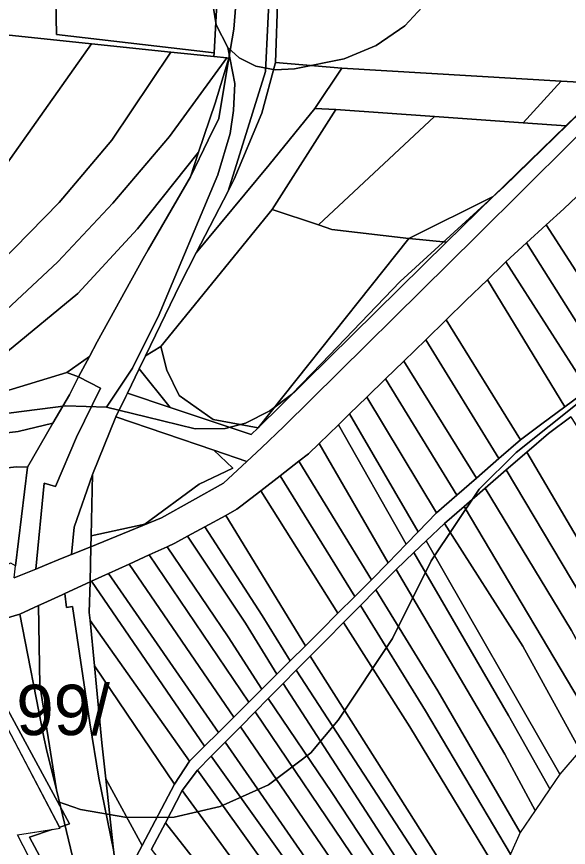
# Model space of a CAD drawing. Extents: x -535894 to -532827, y -1165802 to -1163635.
# Drawn here: x -534273.9 to -534109.5, y -1165431.5 to -1165184 of the extents above; entities that cross this region are included whole.
import ezdxf

# ---------------------------------------------------------------- set-up
doc = ezdxf.new("R2010")
doc.units = 0
for name, color, linetype in [('BPEJ_s', 7, 'Continuous'), ('orna_s', 7, 'Continuous'), ('ostatni_s', 7, 'Continuous'), ('trav_porost_s', 7, 'Continuous'), ('voda_s', 7, 'Continuous')]:
    doc.layers.add(name, color=color, linetype=linetype)

msp = doc.modelspace()

# ---------------------------------------------------------------- linework, layer by layer
at = {"layer": 'BPEJ_s'}
for points in [[(-534128.66, -1165234.701), (-534052.52, -1165160.48), (-533990.56, -1165093.1), (-533942.78, -1165048.02), (-533910.29, -1165011.39), (-533882.731, -1164977.94), (-533858.68, -1164945.769), (-533840.52, -1164915.19)], [(-534304.992, -1164938.782), (-534306.367, -1164946.177), (-534306.73, -1164953.69), (-534305.985, -1164961.176), (-534303.23, -1164969.461), (-534299.169, -1164977.19), (-534280.436, -1165000.199), (-534268.11, -1165013.02), (-534257.59, -1165027.36), (-534248.679, -1165043.835), (-534244.462, -1165051.631), (-534227.57, -1165100.31), (-534222.071, -1165116.16), (-534218.09, -1165134.31), (-534216.18, -1165149.679), (-534216.18, -1165167.13), (-534215.59, -1165178.943), (-534214.43, -1165186.48), (-534210.92, -1165193.25), (-534208.85, -1165204), (-534209.25, -1165212.04), (-534210.291, -1165218.89)], [(-534052.52, -1165160.48), (-534128.66, -1165234.701), (-534159.56, -1165262.93), (-534183.05, -1165287.34), (-534191.96, -1165296.599), (-534198.42, -1165301.519), (-534205.67, -1165305.18), (-534211.72, -1165306.77), (-534220.661, -1165306.853), (-534235.298, -1165303.278), (-534247.08, -1165300.4), (-534239.36, -1165288.81), (-534232.654, -1165275.407), (-534231.71, -1165273.52), (-534213.95, -1165231.16), (-534210.291, -1165218.89), (-534209.25, -1165212.04), (-534208.85, -1165204), (-534210.92, -1165193.25), (-534207.58, -1165196.35), (-534202.56, -1165198.82), (-534196.866, -1165199.921), (-534191.077, -1165199.577), (-534176.28, -1165196.59), (-534166.72, -1165192.69), (-534158.213, -1165186.838), (-534153.03, -1165181.22)], [(-533970.41, -1165171.07), (-533985.872, -1165188.218), (-533999.16, -1165206.031), (-534009.91, -1165220.44), (-534020.91, -1165231.99), (-534035.084, -1165244.865), (-534056.9, -1165261.54), (-534075.955, -1165274.993), (-534079.332, -1165277.377), (-534105.4, -1165298.17), (-534125.07, -1165313.86), (-534136.06, -1165324.773), (-534150.4, -1165346.2), (-534161.87, -1165369.29), (-534178.11, -1165393.66), (-534186.226, -1165403.375), (-534198.82, -1165412.93), (-534213.249, -1165419.389), (-534226.966, -1165422.497), (-534241.03, -1165422.65), (-534254.891, -1165420.26), (-534261.74, -1165417.867), (-534281.75, -1165380.99)], [(-534136.06, -1165324.773), (-534125.07, -1165313.86), (-534105.4, -1165298.17), (-534079.332, -1165277.377), (-534075.955, -1165274.993), (-534056.9, -1165261.54), (-534035.084, -1165244.865), (-534020.91, -1165231.99), (-534009.91, -1165220.44), (-533999.16, -1165206.031), (-533985.872, -1165188.218), (-533970.41, -1165171.07)], [(-534153.03, -1165181.22), (-534158.213, -1165186.838), (-534166.72, -1165192.69), (-534176.28, -1165196.59), (-534191.077, -1165199.577), (-534196.866, -1165199.921), (-534202.56, -1165198.82), (-534207.58, -1165196.35), (-534210.92, -1165193.25), (-534214.43, -1165186.48), (-534215.59, -1165178.943)], [(-534210.291, -1165218.89), (-534213.95, -1165231.16), (-534231.71, -1165273.52), (-534232.654, -1165275.407), (-534239.36, -1165288.81), (-534247.08, -1165300.4), (-534259.201, -1165299.977), (-534288.01, -1165303.627)], [(-534504, -1165364.91), (-534479.15, -1165348.82), (-534459.071, -1165335.819), (-534440.92, -1165327.96), (-534400.789, -1165317.92), (-534366.86, -1165313.619), (-534340.91, -1165310.331), (-534288.01, -1165303.627), (-534259.201, -1165299.977), (-534247.08, -1165300.4), (-534235.298, -1165303.278), (-534220.661, -1165306.853), (-534211.72, -1165306.77), (-534205.67, -1165305.18), (-534198.42, -1165301.519), (-534191.96, -1165296.599), (-534183.05, -1165287.34), (-534159.56, -1165262.93), (-534128.66, -1165234.701)], [(-534254.02, -1165458.36), (-534270, -1165428.46), (-534263.286, -1165426.218), (-534260.88, -1165425.85), (-534261.074, -1165425.479), (-534260.433, -1165425.265), (-534258.14, -1165424.5), (-534261.74, -1165417.867), (-534254.891, -1165420.26), (-534241.03, -1165422.65), (-534226.966, -1165422.497), (-534213.249, -1165419.389), (-534198.82, -1165412.93), (-534186.226, -1165403.375), (-534178.11, -1165393.66), (-534161.87, -1165369.29), (-534150.4, -1165346.2), (-534136.06, -1165324.773)], [(-534013.02, -1165333.89), (-534079.092, -1165382.22), (-534081.89, -1165384.25), (-534087.82, -1165388.56), (-534094.23, -1165393.22), (-534100.32, -1165397.66), (-534105.93, -1165402.64), (-534112, -1165409.73), (-534115, -1165414.12), (-534119.41, -1165420.59), (-534123.86, -1165427.13), (-534126.75, -1165433.55)]]:
    msp.add_lwpolyline(points, dxfattribs=at)
for points in [[(-534260.433, -1165425.265), (-534261.074, -1165425.479), (-534278.69, -1165391.9), (-534289.827, -1165368.435), (-534289.197, -1165368.215), (-534287.26, -1165367.54), (-534281.75, -1165380.99), (-534261.74, -1165417.867), (-534258.14, -1165424.5)], [(-534221.041, -1165492.816), (-534221.281, -1165493.132), (-534234.3, -1165490.14), (-534242.12, -1165462.96), (-534244.14, -1165462.64), (-534249.66, -1165461.74), (-534253.34, -1165461.15), (-534256.73, -1165460.61), (-534273.58, -1165427.79), (-534263.286, -1165426.218), (-534270, -1165428.46), (-534254.02, -1165458.36), (-534247.37, -1165459.96), (-534241.8, -1165460.84), (-534239.62, -1165461.22), (-534239.05, -1165464.37), (-534233.37, -1165489.25), (-534231.05, -1165489.74), (-534220.2, -1165491.71)]]:
    msp.add_lwpolyline(points, close=True, dxfattribs=at)
at = {"layer": 'orna_s'}
for points in [[(-534196.09, -1165177.34), (-534144.9, -1165178.54), (-534107.5, -1165181.08), (-534103.37, -1165181.48), (-534078.8, -1165183.83), (-534077.66, -1165183.91), (-534078.91, -1165185.19), (-534097.29, -1165204.09), (-534111.65, -1165203.25), (-534176.94, -1165199.42), (-534196.74, -1165197.75)], [(-534196.74, -1165197.75), (-534176.94, -1165199.42), (-534185.07, -1165211.45), (-534198.6, -1165228.24), (-534220.39, -1165254.46), (-534210.89, -1165236.07), (-534209.06, -1165232.51), (-534200.78, -1165212.83)], [(-534176.94, -1165199.42), (-534111.65, -1165203.25), (-534122.97, -1165215.71), (-534149.39, -1165213.83), (-534178.75, -1165211.76), (-534185.07, -1165211.45)], [(-534111.65, -1165203.25), (-534097.29, -1165204.09), (-534110.19, -1165216.6), (-534122.97, -1165215.71)], [(-534178.75, -1165211.76), (-534149.39, -1165213.83), (-534183.96, -1165246.08), (-534197.75, -1165241.47)], [(-534149.39, -1165213.83), (-534122.97, -1165215.71), (-534110.19, -1165216.6), (-534131.84, -1165237.61), (-534157.06, -1165250.17), (-534179.96, -1165247.42), (-534183.96, -1165246.08)], [(-534105.03, -1165235.88), (-534078.3, -1165276.29), (-534085.13, -1165281.37), (-534090.65, -1165285.49), (-534116.12, -1165246.09), (-534110.88, -1165241.27)], [(-534197.75, -1165241.47), (-534183.96, -1165246.08), (-534179.96, -1165247.42), (-534157.06, -1165250.17), (-534201.96, -1165306.58), (-534215.31, -1165304.06), (-534225.42, -1165296.87), (-534229.16, -1165289.39), (-534230.92, -1165282.33)], [(-534116.12, -1165246.09), (-534090.65, -1165285.49), (-534097.28, -1165290.43), (-534121.92, -1165251.44)], [(-534121.92, -1165251.44), (-534097.28, -1165290.43), (-534103.68, -1165295.19), (-534128.1, -1165257.13)], [(-534128.1, -1165257.13), (-534103.68, -1165295.19), (-534110.5, -1165300.26), (-534133.62, -1165262.47), (-534128.78, -1165257.75)], [(-534140, -1165268.66), (-534133.62, -1165262.47), (-534110.5, -1165300.26), (-534117.37, -1165305.37), (-534123.72, -1165310.1), (-534145.91, -1165274.41)], [(-534151.99, -1165280.33), (-534145.91, -1165274.41), (-534123.72, -1165310.1), (-534130.19, -1165315.73)], [(-534158.49, -1165286.65), (-534151.99, -1165280.33), (-534130.19, -1165315.73), (-534136.84, -1165321.5)], [(-534163.98, -1165291.99), (-534158.49, -1165286.65), (-534136.84, -1165321.5), (-534142.7, -1165326.58)], [(-534169.57, -1165297.42), (-534163.98, -1165291.99), (-534142.7, -1165326.58), (-534148.81, -1165331.89)], [(-534174.7, -1165302.41), (-534169.57, -1165297.42), (-534148.81, -1165331.89), (-534154.19, -1165337.49)], [(-534178, -1165305.62), (-534174.7, -1165302.41), (-534154.19, -1165337.49), (-534157.81, -1165341.24)], [(-534183.78, -1165311.24), (-534178, -1165305.62), (-534157.81, -1165341.24), (-534163.15, -1165346.78)], [(-534186.9, -1165314.27), (-534183.78, -1165311.24), (-534163.15, -1165346.78), (-534168.1, -1165351.81), (-534189.75, -1165316.48)], [(-534195.4, -1165320.86), (-534189.75, -1165316.48), (-534168.1, -1165351.81), (-534173.09, -1165356.78)], [(-534201.15, -1165325.32), (-534195.4, -1165320.86), (-534173.09, -1165356.78), (-534178.13, -1165361.8)], [(-534207.06, -1165329.91), (-534201.15, -1165325.32), (-534178.13, -1165361.8), (-534183.26, -1165366.91), (-534187.85, -1165371.47), (-534211.58, -1165332.65), (-534208.23, -1165330.82)], [(-534217.81, -1165336.04), (-534211.58, -1165332.65), (-534187.85, -1165371.47), (-534192.38, -1165376), (-534200.7, -1165362.44)], [(-534223, -1165338.87), (-534217.81, -1165336.04), (-534200.7, -1165362.44), (-534192.38, -1165376), (-534196.33, -1165379.94), (-534205.7, -1165364.73)], [(-534226.73, -1165340.9), (-534223, -1165338.87), (-534205.7, -1165364.73), (-534196.33, -1165379.94), (-534200.8, -1165384.39), (-534210.88, -1165368.77), (-534229.05, -1165341.96)], [(-534234.4, -1165344.4), (-534229.05, -1165341.96), (-534210.88, -1165368.77), (-534200.8, -1165384.39), (-534204.72, -1165388.29)], [(-534240.38, -1165347.14), (-534234.4, -1165344.4), (-534204.72, -1165388.29), (-534209.19, -1165392.73)], [(-534246.5, -1165349.94), (-534240.38, -1165347.14), (-534209.19, -1165392.73), (-534213.76, -1165397.27)]]:
    msp.add_lwpolyline(points, close=True, dxfattribs=at)
at = {"layer": 'ostatni_s'}
for points in [[(-534197.6, -1165157.43), (-534199.71, -1165200.4), (-534210.89, -1165236.07), (-534220.39, -1165254.46), (-534225.18, -1165263.79), (-534235.49, -1165285.14), (-534237.36, -1165289.01), (-534240.88, -1165296.25), (-534241.33, -1165297.17), (-534244.31, -1165303.28), (-534251.27, -1165320.44), (-534256.77, -1165336.1), (-534257.49, -1165344.29), (-534260.27, -1165345.42), (-534265.54, -1165347.57), (-534268.13, -1165348.62), (-534265.69, -1165323.08), (-534262.28, -1165324.03), (-534256.03, -1165309.32), (-534248.87, -1165294.69), (-534255.45, -1165291.38), (-534252.19, -1165285.28), (-534249.84, -1165280.89), (-534236.16, -1165256.09), (-534234.65, -1165253.49), (-534222.12, -1165231.81), (-534216.81, -1165220.86), (-534213.66, -1165214.35), (-534210.61, -1165196.44), (-534209.14, -1165187.8), (-534208.19, -1165175.29)], [(-534066.72, -1165179.82), (-534136.8, -1165249.37), (-534194.29, -1165306.12), (-534200.89, -1165312.54), (-534205.31, -1165316.61), (-534215.14, -1165313.24), (-534244.31, -1165303.28), (-534241.33, -1165297.17), (-534240.88, -1165296.25), (-534228.15, -1165300.5), (-534203.98, -1165308.56), (-534201.96, -1165306.58), (-534145.83, -1165251.25), (-534131.84, -1165237.61), (-534110.19, -1165216.6), (-534097.29, -1165204.09), (-534078.91, -1165185.19), (-534077.66, -1165183.91)], [(-534306.94, -1165304.65), (-534258.88, -1165290.11), (-534255.45, -1165291.38), (-534258.18, -1165296.74), (-534263.07, -1165305.2), (-534273.43, -1165307.68), (-534336.76, -1165315.12)], [(-534243.4, -1165444.03), (-534236.52, -1165431.02), (-534226.8, -1165412.68), (-534222.38, -1165405.86), (-534217.91, -1165401.41), (-534213.76, -1165397.27), (-534209.19, -1165392.73), (-534204.72, -1165388.29), (-534200.8, -1165384.39), (-534196.33, -1165379.94), (-534192.38, -1165376), (-534187.85, -1165371.47), (-534183.26, -1165366.91), (-534178.13, -1165361.8), (-534173.09, -1165356.78), (-534168.1, -1165351.81), (-534163.15, -1165346.78), (-534157.81, -1165341.24), (-534154.19, -1165337.49), (-534148.81, -1165331.89), (-534142.7, -1165326.58), (-534136.84, -1165321.5), (-534130.19, -1165315.73), (-534123.72, -1165310.1), (-534117.37, -1165305.37), (-534110.5, -1165300.26), (-534103.68, -1165295.19)], [(-534108.76, -1165303.24), (-534115.44, -1165308.22), (-534121.89, -1165313.8), (-534128.01, -1165319.11), (-534134.26, -1165324.52), (-534140.55, -1165329.98), (-534146.4, -1165335.06), (-534151.85, -1165340.25), (-534155.49, -1165343.73), (-534160.76, -1165348.75), (-534166.84, -1165354.83), (-534171.44, -1165359.48), (-534176.44, -1165364.53), (-534181.53, -1165369.66), (-534186.43, -1165374.61), (-534190.57, -1165378.79), (-534194.5, -1165382.75), (-534198.92, -1165387.21), (-534202.8, -1165391.13), (-534207.22, -1165395.6), (-534211.75, -1165400.17), (-534215.9, -1165404.37), (-534220.02, -1165408.52), (-534224.52, -1165414.59), (-534229.56, -1165424.19), (-534233.69, -1165432.05)], [(-534551.38, -1165379.05), (-534422.4, -1165326.53), (-534364.57, -1165315.97), (-534336.76, -1165315.12), (-534273.43, -1165307.68), (-534263.07, -1165305.2), (-534270.61, -1165318.24), (-534273.89, -1165318.16), (-534312.18, -1165322.29), (-534336.67, -1165324.94), (-534360.45, -1165326.25), (-534364.65, -1165326.48), (-534419.17, -1165333.25), (-534502.24, -1165366.65)]]:
    msp.add_lwpolyline(points, dxfattribs=at)
for points in [[(-534213.26, -1165156.72), (-534209.51, -1165156.58), (-534208.19, -1165175.29), (-534209.14, -1165187.8), (-534210.61, -1165196.44), (-534211.25, -1165196.37), (-534215.09, -1165195.97), (-534215.04, -1165194.82), (-534213.98, -1165174.68)], [(-534196.09, -1165177.34), (-534196.74, -1165197.75), (-534200.78, -1165212.83), (-534209.06, -1165232.51), (-534210.89, -1165236.07), (-534199.71, -1165200.4), (-534197.6, -1165157.43)], [(-534214.76, -1165209.81), (-534210.61, -1165196.44), (-534213.66, -1165214.35), (-534216.81, -1165220.86), (-534222.12, -1165231.81), (-534219.65, -1165224.42)], [(-534185.07, -1165211.45), (-534178.75, -1165211.76), (-534197.75, -1165241.47), (-534230.92, -1165282.33), (-534235.49, -1165285.14), (-534225.18, -1165263.79), (-534220.39, -1165254.46), (-534198.6, -1165228.24)], [(-534235.49, -1165285.14), (-534230.92, -1165282.33), (-534229.16, -1165289.39), (-534225.42, -1165296.87), (-534215.31, -1165304.06), (-534201.96, -1165306.58), (-534203.98, -1165308.56), (-534228.15, -1165300.5), (-534237.36, -1165289.01)], [(-534240.88, -1165296.25), (-534237.36, -1165289.01), (-534228.15, -1165300.5)], [(-534248.87, -1165294.69), (-534256.03, -1165309.32), (-534262.28, -1165324.03), (-534265.69, -1165323.08), (-534268.13, -1165348.62), (-534274.64, -1165351.27), (-534274.2, -1165347.69), (-534270.61, -1165318.24), (-534263.07, -1165305.2), (-534258.18, -1165296.74), (-534255.45, -1165291.38)], [(-534215.14, -1165313.24), (-534209.48, -1165318.59), (-534219.52, -1165323.38), (-534235.68, -1165335.21), (-534251.69, -1165338.72), (-534251.27, -1165320.44), (-534244.31, -1165303.28)], [(-534205.31, -1165316.61), (-534212.27, -1165323.02), (-534230.69, -1165333.38), (-534251.77, -1165341.96), (-534251.69, -1165338.72), (-534235.68, -1165335.21), (-534219.52, -1165323.38), (-534209.48, -1165318.59), (-534215.14, -1165313.24)], [(-534273.89, -1165318.16), (-534270.61, -1165318.24), (-534274.2, -1165347.69), (-534275.59, -1165346.89), (-534279.12, -1165348.18), (-534284.53, -1165354.73), (-534300.23, -1165360.21), (-534301.65, -1165360.47), (-534307.88, -1165340.19), (-534312.18, -1165322.29)], [(-534256.77, -1165336.1), (-534251.27, -1165320.44), (-534251.69, -1165338.72), (-534251.77, -1165341.96), (-534257.49, -1165344.29)], [(-534259.48, -1165355.88), (-534252.01, -1165352.47), (-534252.23, -1165361.54), (-534251.99, -1165363.99), (-534250.69, -1165377.47), (-534248.48, -1165400.41), (-534247.31, -1165411.07), (-534244.98, -1165432.27), (-534249.38, -1165410.91), (-534252.04, -1165394.43), (-534257.28, -1165359.81), (-534259.04, -1165360.05)], [(-534260.34, -1165356.27), (-534259.48, -1165355.88), (-534259.04, -1165360.05), (-534257.28, -1165359.81), (-534252.04, -1165394.43), (-534249.38, -1165410.91), (-534244.98, -1165432.27), (-534243.4, -1165444.03), (-534242.7, -1165449.22), (-534241.22, -1165460.36), (-534234.3, -1165490.14), (-534242.12, -1165462.96), (-534244.14, -1165462.64), (-534249.66, -1165461.74), (-534253.34, -1165461.15), (-534257.19, -1165434.29), (-534262.04, -1165414.36), (-534266.94, -1165383.2), (-534267.32, -1165359.47), (-534265.74, -1165358.75), (-534264.71, -1165358.28)], [(-534272.9, -1165362.02), (-534267.32, -1165359.47), (-534266.94, -1165383.2), (-534262.04, -1165414.36), (-534264.94, -1165402.42), (-534265.72, -1165399.2)], [(-534272.9, -1165362.02), (-534265.72, -1165399.2), (-534264.94, -1165402.42), (-534262.04, -1165414.36), (-534257.19, -1165434.29), (-534253.34, -1165461.15), (-534256.73, -1165460.61), (-534273.58, -1165427.79), (-534260.88, -1165425.85), (-534278.69, -1165391.9), (-534290.38, -1165367.27), (-534285.88, -1165365.91), (-534282.54, -1165366.1), (-534281.74, -1165364.67)], [(-534248.48, -1165400.41), (-534250.69, -1165377.47), (-534226.8, -1165412.68), (-534236.52, -1165431.02), (-534247.31, -1165411.07)], [(-534247.31, -1165411.07), (-534236.52, -1165431.02), (-534243.4, -1165444.03), (-534244.98, -1165432.27)]]:
    msp.add_lwpolyline(points, close=True, dxfattribs=at)
at = {"layer": 'trav_porost_s'}
for points in [[(-534262.3, -1165174.22), (-534262, -1165189.37), (-534215.04, -1165194.82), (-534215.09, -1165195.97), (-534227.96, -1165194.63), (-534251.58, -1165192.19), (-534277.01, -1165189.45), (-534305.54, -1165188.53), (-534335.39, -1165187.36), (-534335.9, -1165174.28)], [(-534262.3, -1165174.22), (-534234.38, -1165174.49), (-534213.98, -1165174.68), (-534215.04, -1165194.82), (-534262, -1165189.37)], [(-534251.58, -1165192.19), (-534282.29, -1165235.45), (-534304.8, -1165266.72), (-534331.16, -1165286.47), (-534333.44, -1165283.8), (-534338.28, -1165279.56), (-534313.06, -1165256.19), (-534303.23, -1165237.18), (-534292.35, -1165221.02), (-534277.01, -1165189.45)], [(-534227.96, -1165194.63), (-534245.56, -1165220.9), (-534261.17, -1165239.42), (-534283.59, -1165262.17), (-534299.13, -1165278.61), (-534326.29, -1165293.35), (-534328.82, -1165289.63), (-534331.16, -1165286.47), (-534304.8, -1165266.72), (-534282.29, -1165235.45), (-534251.58, -1165192.19)], [(-534215.09, -1165195.97), (-534211.25, -1165196.37), (-534228.29, -1165219.76), (-534245.24, -1165239.58), (-534261.59, -1165257.06), (-534283.02, -1165277.03), (-534295.94, -1165285.41), (-534322.34, -1165299.19), (-534326.29, -1165293.35), (-534299.13, -1165278.61), (-534283.59, -1165262.17), (-534261.17, -1165239.42), (-534245.56, -1165220.9), (-534227.96, -1165194.63)], [(-534210.61, -1165196.44), (-534214.76, -1165209.81), (-534219.65, -1165224.42), (-534237.87, -1165247.3), (-534255.61, -1165266.55), (-534276.57, -1165283.84), (-534299.11, -1165296.92), (-534308.52, -1165299.61), (-534320.19, -1165302.94), (-534321.2, -1165301.18), (-534322.34, -1165299.19), (-534295.94, -1165285.41), (-534283.02, -1165277.03), (-534261.59, -1165257.06), (-534245.24, -1165239.58), (-534228.29, -1165219.76), (-534211.25, -1165196.37)], [(-534222.12, -1165231.81), (-534234.65, -1165253.49), (-534236.16, -1165256.09), (-534249.84, -1165280.89), (-534252.19, -1165285.28), (-534258.88, -1165290.11), (-534306.94, -1165304.65), (-534308.52, -1165299.61), (-534299.11, -1165296.92), (-534276.57, -1165283.84), (-534255.61, -1165266.55), (-534237.87, -1165247.3), (-534219.65, -1165224.42)], [(-534157.06, -1165250.17), (-534131.84, -1165237.61), (-534145.83, -1165251.25), (-534156.94, -1165250.18)], [(-534157.06, -1165250.17), (-534156.94, -1165250.18), (-534145.83, -1165251.25), (-534201.96, -1165306.58)], [(-534258.88, -1165290.11), (-534252.19, -1165285.28), (-534255.45, -1165291.38)], [(-534108.76, -1165303.24), (-534079.55, -1165350.17), (-534067.65, -1165373.91), (-534075.22, -1165379.41), (-534081.89, -1165384.25), (-534095.85, -1165358.13), (-534121.89, -1165313.8), (-534115.44, -1165308.22)], [(-534128.01, -1165319.11), (-534121.89, -1165313.8), (-534095.85, -1165358.13), (-534081.89, -1165384.25), (-534087.82, -1165388.56), (-534103.02, -1165361.05)], [(-534134.26, -1165324.52), (-534128.01, -1165319.11), (-534103.02, -1165361.05), (-534087.82, -1165388.56), (-534094.23, -1165393.22), (-534108.57, -1165366.89)], [(-534140.55, -1165329.98), (-534134.26, -1165324.52), (-534108.57, -1165366.89), (-534094.23, -1165393.22), (-534100.32, -1165397.66)], [(-534146.4, -1165335.06), (-534140.55, -1165329.98), (-534100.32, -1165397.66), (-534105.93, -1165402.64), (-534123.09, -1165371.57)], [(-534151.85, -1165340.25), (-534146.4, -1165335.06), (-534123.09, -1165371.57), (-534105.93, -1165402.64), (-534112, -1165409.73)], [(-534155.49, -1165343.73), (-534151.85, -1165340.25), (-534112, -1165409.73), (-534115, -1165414.12), (-534127.3, -1165392.23)], [(-534160.76, -1165348.75), (-534155.49, -1165343.73), (-534127.3, -1165392.23), (-534115, -1165414.12), (-534119.41, -1165420.59), (-534128.46, -1165403.74)], [(-534251.58, -1165352.26), (-534246.5, -1165349.94), (-534213.76, -1165397.27), (-534217.91, -1165401.41)], [(-534166.84, -1165354.83), (-534160.76, -1165348.75), (-534128.46, -1165403.74), (-534119.41, -1165420.59), (-534123.86, -1165427.13), (-534148.33, -1165384.9)], [(-534252.01, -1165352.47), (-534251.58, -1165352.26), (-534217.91, -1165401.41), (-534222.38, -1165405.86), (-534251.99, -1165363.99), (-534252.23, -1165361.54)], [(-534171.44, -1165359.48), (-534166.84, -1165354.83), (-534148.33, -1165384.9), (-534123.86, -1165427.13), (-534126.75, -1165433.55), (-534152.03, -1165390.89)], [(-534176.44, -1165364.53), (-534171.44, -1165359.48), (-534152.03, -1165390.89), (-534126.75, -1165433.55), (-534129.01, -1165441.31), (-534156.72, -1165395.63)], [(-534250.69, -1165377.47), (-534251.99, -1165363.99), (-534222.38, -1165405.86), (-534226.8, -1165412.68)], [(-534181.53, -1165369.66), (-534176.44, -1165364.53), (-534156.72, -1165395.63), (-534129.01, -1165441.31), (-534131.39, -1165449.51), (-534133.74, -1165457.61), (-534186.43, -1165374.61)], [(-534190.57, -1165378.79), (-534186.43, -1165374.61), (-534133.74, -1165457.61), (-534135.45, -1165463.49)], [(-534194.5, -1165382.75), (-534190.57, -1165378.79), (-534135.45, -1165463.49), (-534137.53, -1165470.62)], [(-534198.92, -1165387.21), (-534194.5, -1165382.75), (-534137.53, -1165470.62), (-534139.34, -1165476.85), (-534179.96, -1165415.17)], [(-534202.8, -1165391.13), (-534198.92, -1165387.21), (-534179.96, -1165415.17), (-534139.34, -1165476.85), (-534140.98, -1165482.5)], [(-534207.22, -1165395.6), (-534202.8, -1165391.13), (-534140.98, -1165482.5), (-534142.99, -1165489.42)], [(-534211.75, -1165400.17), (-534207.22, -1165395.6), (-534142.99, -1165489.42), (-534144.9, -1165495.99), (-534170.58, -1165458.63), (-534182.69, -1165442.19)], [(-534215.9, -1165404.37), (-534211.75, -1165400.17), (-534182.69, -1165442.19), (-534170.58, -1165458.63), (-534144.9, -1165495.99), (-534146.71, -1165502.23), (-534170.82, -1165467.44)], [(-534220.02, -1165408.52), (-534215.9, -1165404.37), (-534170.82, -1165467.44), (-534146.71, -1165502.23), (-534148.5, -1165508.42)], [(-534224.52, -1165414.59), (-534220.02, -1165408.52), (-534148.5, -1165508.42), (-534150.66, -1165515.85)], [(-534229.56, -1165424.19), (-534224.52, -1165414.59), (-534150.66, -1165515.85), (-534153.04, -1165524.07), (-534181.38, -1165485.61)], [(-534233.69, -1165432.05), (-534229.56, -1165424.19), (-534181.38, -1165485.61), (-534153.04, -1165524.07), (-534155.94, -1165534.08), (-534184.87, -1165495.38)]]:
    msp.add_lwpolyline(points, close=True, dxfattribs=at)
at = {"layer": 'voda_s'}
for points in [[(-534105.03, -1165235.88), (-534110.88, -1165241.27), (-534116.12, -1165246.09), (-534121.92, -1165251.44), (-534128.1, -1165257.13), (-534128.78, -1165257.75), (-534133.62, -1165262.47), (-534140, -1165268.66), (-534145.91, -1165274.41), (-534151.99, -1165280.33), (-534158.49, -1165286.65), (-534163.98, -1165291.99), (-534169.57, -1165297.42), (-534174.7, -1165302.41), (-534178, -1165305.62), (-534183.78, -1165311.24), (-534186.9, -1165314.27), (-534189.75, -1165316.48), (-534195.4, -1165320.86), (-534201.15, -1165325.32), (-534207.06, -1165329.91), (-534208.23, -1165330.82), (-534211.58, -1165332.65), (-534217.81, -1165336.04), (-534223, -1165338.87), (-534226.73, -1165340.9), (-534229.05, -1165341.96), (-534234.4, -1165344.4), (-534240.38, -1165347.14), (-534246.5, -1165349.94), (-534251.58, -1165352.26), (-534252.01, -1165352.47), (-534251.77, -1165341.96), (-534230.69, -1165333.38), (-534212.27, -1165323.02), (-534205.31, -1165316.61), (-534200.89, -1165312.54), (-534194.29, -1165306.12), (-534136.8, -1165249.37), (-534066.72, -1165179.82)], [(-534274.64, -1165351.27), (-534268.13, -1165348.62), (-534265.54, -1165347.57), (-534260.27, -1165345.42), (-534257.49, -1165344.29), (-534251.77, -1165341.96), (-534252.01, -1165352.47), (-534259.48, -1165355.88), (-534260.34, -1165356.27), (-534264.71, -1165358.28), (-534265.74, -1165358.75), (-534267.32, -1165359.47), (-534272.9, -1165362.02), (-534281.74, -1165364.67)]]:
    msp.add_lwpolyline(points, dxfattribs=at)

# ---------------------------------------------------------------- texts
at = {"layer": 'BPEJ_s'}
msp.add_text('99/', height=15, dxfattribs=at).set_placement((-534273.984, -1165398.087))

doc.saveas('drawing.dxf')
